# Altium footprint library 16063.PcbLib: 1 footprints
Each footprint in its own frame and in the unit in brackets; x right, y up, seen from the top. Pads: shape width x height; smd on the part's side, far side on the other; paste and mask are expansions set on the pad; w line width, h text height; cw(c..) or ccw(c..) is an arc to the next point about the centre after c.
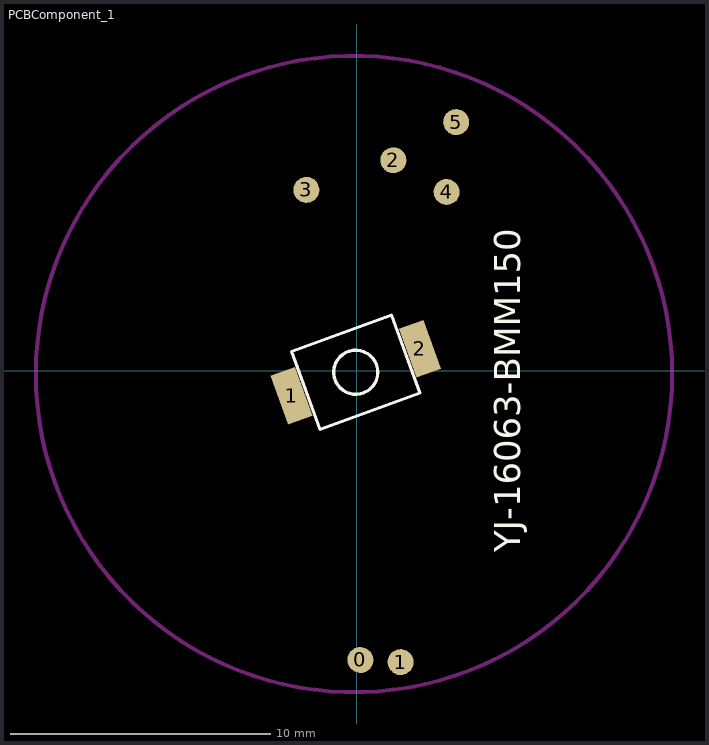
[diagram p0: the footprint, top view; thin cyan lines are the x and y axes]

## PCBComponent_1 [mm]
pads (8):
  round 1 smd: 0(0.14,-11.141) 1(1.69,-11.221) 2(1.41,8.099) 3(-1.94,6.959) 4(3.46,6.879) 5(3.83,9.569)
  rect 2x1 smd rot 110: 1(-2.508,-0.967) 2(2.432,0.841)
Top Overlay:
  circle w0.127: c-0.038,-0.063 r0.85
  lines w0.127: -2.511,0.74 -1.417,-2.267 2.436,-0.865 1.341,2.142 -2.511,0.74
  text "YJ-16063-BMM150" at 6.3,-6.991 h1
Keep-Out Layer:
  circle w0.152: c-0.106,-0.13 r12.25
3D body: height 1.8, standoff 0, extent -2.517,-2.27 2.444,2.145
3D body: height 0.1, standoff 0, extent 1.587,-0.155 3.043,1.742
3D body: height 0.1, standoff 0, extent -3.151,-1.879 -1.695,0.017
3D body: height 2.3, standoff 1.8, extent -1.31,-1.339 1.245,1.218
